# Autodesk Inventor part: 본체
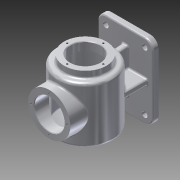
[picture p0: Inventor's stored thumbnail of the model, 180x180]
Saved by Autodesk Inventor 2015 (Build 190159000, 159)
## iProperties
Created: 2016-09
Part Number: 본체
Material: 알루미늄 6061
Document SubType Name: Modeling
Designer: LineLG02
Density: 2.7 g/cm^3
Appearance: 알루미늄 - 평지
Mass: 969.057 g
Surface Area: 1287.67 cm^2
Volume: 358.91 cm^3
Author: LineLG02
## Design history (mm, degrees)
sketch "스케치1"
  geometry: L1 (0, 0)-(0, 122); L2 (0, 122)-(38, 122); L3 (38, 122)-(38, 110); L4 (38, 110)-(45, 110); L5 (0, 0)-(38, 0); L6 (50, 14.626)-(50, 22); L7 (50, 14.626)-(50, 105); A1 r 115 centre (0, 115) between (0, 0) and (47.045, 10.063); A2 r 5 centre (45, 105) between (50, 105) and (45, 110); A3 r 5 centre (45, 14.626) between (47.045, 10.063) and (50, 14.626); 1 further point
  constraints: 14 end point, 7 point on circle, 5 tangent, 3 centre point, 3 point on line, 2 horizontal, 2 parallel, 2 perpendicular, 1 equal radius, 1 vertical
  dimensions: "d0" = 122 distance of L1.start L1.end; "d11" = 5 radius of A2
revolve "회전1" sketch "스케치1" stored, may be unused: angle "d12" = 90 deg
sketch "스케치2"
  geometry: L1 (0, 0)-(0, 122); L2 (-27, 107)-(-27, 122); L3 (-27, 107)-(-45, 107); L4 (-47, 105)-(-47, 14.626); L5 (-50, 105)-(-50, 14.626) reference; L6 (0, 122)-(-27, 122); A1 r 115 centre (0, 115) between (-47.045, 10.063) and (47.045, 10.063) reference; A2 r 5 centre (-45, 14.626) between (-50, 14.626) and (-47.045, 10.063) reference; A3 r 112 centre (0, 115) between (-45.818, 12.801) and (0, 3); A4 r 2 centre (-45, 105) between (-45, 107) and (-47, 105); A5 r 2 centre (-45, 14.626) between (-47, 14.626) and (-45.818, 12.801); 1 further point
  constraints: 10 end point, 7 point on circle, 4 tangent, 3 centre point, 2 horizontal, 2 point on line, 1 equal radius, 1 parallel, 1 perpendicular, 1 vertical
  dimensions: "d17" = 3 radial gap between concentric circles of A1 A3; "d19" = 2 radius of A4
revolve "회전2" sketch "스케치2" stored, may be unused: angle "d20" = 90 deg
node "작업 평면1"
sketch "스케치3"
  geometry: L1 (-38, 122)-(38, 122) reference; L2 (-38, 60)-(38, 60); C1 r 38 at (0, 60); 1 further point
  constraints: 2 end point, 1 centre point, 1 midpoint, 1 parallel
  dimensions: "d22" = 62 distance between parallel lines of L1 L2; "d23" = 76 diameter of C1
extrude "돌출1" join sketch "스케치3" stored distance "d24" = 10; taper "d25" = 0 deg
sketch "스케치4"
  geometry: C1 r 38 at (0, 0) reference; C2 r 27 at (0, 0); 1 further point
  constraints: 1 centre point, 1 coincident
  dimensions: "d26" = 54 diameter of C2
extrude "돌출2" cut sketch "스케치4" stored distance "d27" = 10; taper "d28" = 0 deg
node "작업 평면2"
sketch "스케치5"
  geometry: L1 (-38, 62)-(38, 62) reference; L2 (-50, 68.5)-(50, 68.5); L3 (50, 68.5)-(50, -66.5); L4 (50, -66.5)-(-50, -66.5); L5 (-50, -66.5)-(-50, 68.5); L6 (-50, 68.5)-(50, -66.5); L7 (50, 68.5)-(-50, -66.5); 2 further points
  constraints: 12 end point, 2 midpoint, 2 parallel, 1 horizontal, 1 perpendicular
  dimensions: "d30" = 100 distance of L3.end L4.end; "d31" = 135 distance of L2.end L3.end
extrude "돌출3" join sketch "스케치5" distance "d32" = 10; taper "d33" = 0 deg
node "작업 평면3"
sketch "스케치6"
  geometry: L1 (107.5, -10)-(105.482, -33.062); L2 (107.5, -10)-(27.5, -10); L3 (27.5, -10)-(29.518, -33.062); L4 (105.482, -33.062)-(29.518, -33.062); 3 further points
  constraints: 8 end point, 2 horizontal
  dimensions: "d44" = 95 deg angle of L2 L1; "d45" = 95 deg angle of L2 L3
extrude "돌출4" join sketch "스케치6" stored distance "d46" = 10; taper "d47" = 0 deg
node "작업 평면4"
sketch "스케치7"
  geometry: L1 (100, 0)-(100, -10) reference; L2 (50, 0)-(50, -10); L3 (90, 0)-(90, -54.513); L4 (10, 0)-(10, -10); L5 (10, -10)-(10, -54.513); L6 (10, -10)-(90, -10); L7 (100, -10)-(0, -10) reference; A1 r 48.534 centre (50, -82) between (90, -54.513) and (10, -54.513); 1 further point
  constraints: 10 end point, 3 parallel, 2 point on circle, 2 point on line, 1 centre point, 1 coincident, 1 vertical
  dimensions: "d48" = 50 distance between parallel lines of L1 L2; "d49" = 40 distance between parallel lines of L2 L3; "d50" = 40 distance between parallel lines of L2 L4
extrude "돌출5" join sketch "스케치7" stored distance "d51" = 10; taper "d52" = 0 deg
sketch "스케치8"
  geometry: L1 (50, 68.5)-(50, -66.5) reference; L2 (-50, 68.5)-(50, 68.5) reference; L3 (50, 68.5)-(50, -66.5) reference; L4 (50, -66.5)-(-50, -66.5) reference; L5 (-50, -66.5)-(-50, 68.5) reference; L6 (50, 68.5)-(35, 68.5); L7 (-35, 68.5)-(-50, 68.5); L8 (50, -66.5)-(50, -51.5); L9 (50, 53.5)-(50, 68.5); L10 (-50, -66.5)-(-35, -66.5); L11 (35, -66.5)-(50, -66.5); L12 (-50, 68.5)-(-50, 53.5); L13 (-50, -51.5)-(-50, -66.5); A1 r 15 centre (35, 53.5) between (50, 53.5) and (35, 68.5); A2 r 15 centre (-35, 53.5) between (-35, 68.5) and (-50, 53.5); A3 r 15 centre (35, -51.5) between (35, -66.5) and (50, -51.5); A4 r 15 centre (-35, -51.5) between (-50, -51.5) and (-35, -66.5); 1 further point
  constraints: 16 end point, 8 parallel, 8 point on circle, 8 tangent, 4 centre point, 4 perpendicular, 2 horizontal
  dimensions: "d53" = 15 radius of A1; "d54" = 15 radius of A2; "d55" = 15 radius of A3; "d56" = 15 radius of A4
extrude "돌출6" cut sketch "스케치8" stored distance "d57" = 10; taper "d58" = 0 deg
sketch "스케치9"
  geometry: A1 r 15 centre (35, 53.5) between (50, 53.5) and (35, 68.5) reference; A2 r 15 centre (-35, 53.5) between (-35, 68.5) and (-50, 53.5) reference; A3 r 15 centre (-35, -51.5) between (-50, -51.5) and (-35, -66.5) reference; A4 r 15 centre (35, -51.5) between (35, -66.5) and (50, -51.5) reference; 1 further point
hole "구멍1" sketch "스케치9" at (35, 53.5), (-35, 53.5), (-35, -51.5), (35, -51.5) diameter "d59" = 10; stored, may be unused: countersink angle "d63" = 90 deg, drill point angle "d65" = 0 deg; dims "d60" = 6, "d61" = 4, "d62" = 2, "d64" = 8
sketch "스케치10" dims "d66" = 65
  geometry: L1 (0, 0)-(0, -41.057); 2 further points
  constraints: 2 end point, 1 coincident, 1 point on line, 1 vertical, 1 vertical alignment, 2 other
hole "구멍2" sketch "스케치10" at (0, -32.5) diameter "d67" = 3.242; stored, may be unused: countersink angle "d71" = 90 deg, drill point angle "d73" = 118 deg; dims "d68" = 8, "d69" = 4, "d70" = 2, "d72" = 10
sketch "스케치11" dims "d77" = 65
  geometry: L1 (0, 0)-(0, 34.462); C1 r 38 at (0, 0) reference; 2 further points
  constraints: 2 end point, 1 coincident, 1 point on line, 1 vertical, 1 vertical alignment, 2 other
hole "구멍3" sketch "스케치11" at (0, 32.5) diameter "d78" = 3.242; stored, may be unused: countersink angle "d82" = 90 deg, drill point angle "d84" = 118 deg; dims "d79" = 8, "d80" = 4, "d81" = 2, "d83" = 10
chamfer "모따기1" distance "d88" = 1; stored, may be unused: second distance "d89" = 2, angle "d90" = 45 deg
chamfer "모따기2" distance "d91" = 1; stored, may be unused: second distance "d92" = 2, angle "d93" = 45 deg
fillet "모깎기1" dims "d94" = 3
node "작업 평면10"
  node "작업 평면9"
sketch "스케치15"
  geometry: 2 further points
  constraints: 1 coincident, 1 other
extrude "돌출7" join sketch "스케치15" stored distance "d98" = 10; taper "d99" = 0 deg
fillet "모깎기2" dims "d100" = 3
node "솔리드1"
pattern_circular "원형 패턴1" dims angle "d75" = 360 deg
pattern_circular "원형 패턴2" dims angle "d86" = 360 deg
node "투영된 루프1"
node "투영된 루프2"
other parameters: "d21" = -65, "d29" = -147, "d97" = 0.5
